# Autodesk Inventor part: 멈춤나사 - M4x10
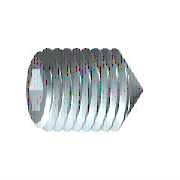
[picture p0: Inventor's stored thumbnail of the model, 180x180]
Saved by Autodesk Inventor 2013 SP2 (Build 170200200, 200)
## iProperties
Created: 2012-02
Part Number: 멈춤나사 - M4x10
Material: 강철, 연강
Description: 6각 소켓 머리 없는 멈춤 나사
Document SubType Name: Modeling
Standard: KS B 1028
Designer: mduedu
Standards Organization: KS
Language: ko-KR
Size Designation: 원추점 M4x10
Categories: <MemberInstance><Categories><Category DisplayName="조임쇠" InternalName="e4da775c-781d-43d5-af7c-5136215cf5a6" Mnemonic="FSTN"><Category DisplayName="볼트" InternalN
Density: 7.86 g/cm^3
Mass: 0.792069 g
Surface Area: 1.48192 cm^2
Volume: 0.100772 cm^3
Author: mduedu
IsCustomPart: 1
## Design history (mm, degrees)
sketch "스케치1"
  geometry: L1 (0, 0)-(6.833, 0); L2 (10, 1.155)-(10, 2); L3 (10, 2)-(0, 2); L4 (10, 1.155)-(7.5, 1.155); L5 (7.5, 1.155)-(6.833, 0); L6 (0, -0.4)-(0, 2.4) reference; L7 (0, 2)-(0, 0)
  constraints: 13 end point, 3 parallel, 1 collinear, 1 perpendicular, 1 point on line
  dimensions: "d0" = 2.5 distance of L2.start L4.end (= INTI); "d1" = 60 deg angle of L5 L1; "d2" = 4 diameter of L3 L1 (= NND); "d3" = 2.3094 diameter of L4 L1 (= 1.1547 x SW); "d5" = 10 distance from line of L2 L3.end (= NLG)
revolve "본체" sketch "스케치1" stored, may be unused: angle "d6" = 90 deg
sketch "스케치2"
  geometry: L1 (-0.577, 1)-(0.577, 1); L2 (0.577, 1)-(1.155, 0); L3 (1.155, 0)-(0.577, -1); L4 (0.577, -1)-(-0.577, -1); L5 (-0.577, -1)-(-1.155, 0); L6 (-1.155, 0)-(-0.577, 1); 3 further points
  constraints: 12 end point, 1 coincident, 1 horizontal, 13 other
extrude "슬롯" join sketch "스케치2" taper "d7" = 0 deg; stored distance "d21" = 10
workaxis "Work Axis1"
workplane "Work Plane1"
sketch "스케치4"
  geometry: L1 (-5, 0.2)-(-3.2, 2) reference; L2 (-5, -0.2)-(-3.2, -2) reference; L3 (-3.2, 2)-(-5.2, 0); L4 (-3.2, -2)-(-5.2, 0); 2 further points
  constraints: 4 end point, 2 collinear, 1 coincident
body "Solid1"
feature "스레드" dims "d12" = 10 (= NLG), "d13" = 0
chamfer "모따기1" distance "d8" = 1.8 (computed from NND, SPD, FAWI); stored, may be unused: angle "d9" = 45 deg (= FAWI), second distance "d34" = 1.8 (computed from NND, SPD, FAWI)
chamfer "모따기2" distance "d10" = 0.42941 (= -0.5 x GD1 + 0.5 x NND); stored, may be unused: angle "d11" = 45 deg (= FAWI), second distance "d35" = 0.42941 (= -0.5 x GD1 + 0.5 x NND)
other parameters: "NND" = 4 [user parameter; used in 5 equation terms], "NLG" = 10 [user parameter; used in 2 equation terms], "INTI" = 2.5 [user parameter; used in 1 equation term], "FAWI" = 45 deg [user parameter; used in 4 equation terms], "SW" = 2 [user parameter; used in 2 equation terms], "GD1" = 3.14117 (= THREADDIA - 1.2269 x PTC) [user parameter; used in 2 equation terms], "d4" = 0, "FAWI1" = 45 deg [user parameter], "SPD" = 0.4 [user parameter; used in 2 equation terms], "d36" = 0, "d37" = 0, "GUL" = 0.42941 (= 0.61345 x PTC) [user parameter], "TPU" = 14.28571 (computed from PTC) [user parameter], "TOA" = 30 deg [user parameter], "THREADDIA" = 4 [user parameter; used in 1 equation term], "PTC" = 0.7 [user parameter; used in 4 equation terms], "GAL" = 0.42941 (= 0.61345 x PTC) [user parameter], "E0" = 2.31 (= 1.155 x SW) [user parameter]
